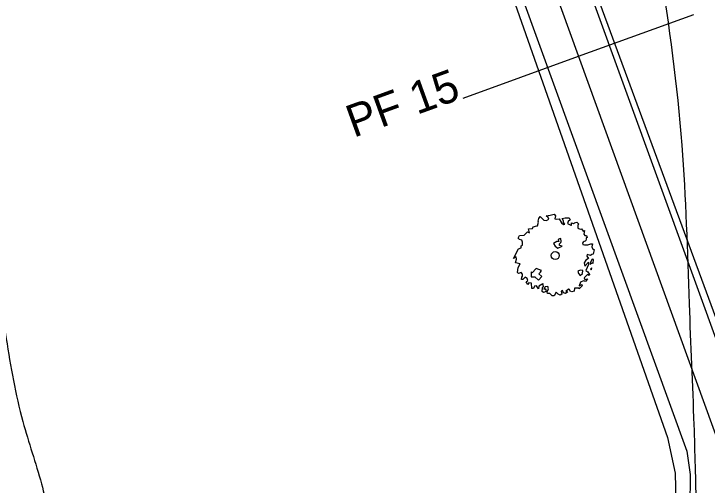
# Model space of a CAD drawing. Extents: x -475575 to -473225, y -1116053 to -1114104.
# Drawn here: x -474251.65 to -474209.3, y -1115030.45 to -1115001.67 of the extents above; entities that cross this region are included whole.
import ezdxf

# ---------------------------------------------------------------- set-up
doc = ezdxf.new("R2010")
doc.units = 0
for name, color, linetype in [('CESTN___P____KOP_N__VRH__Construction_', 7, 'Continuous'), ('IP', 7, 'Continuous'), ('POLYGONY_SITUACE_PF', 7, 'Continuous'), ('POLYGONY_SITUACE_PF_POPISY', 7, 'Continuous'), ('POLYGONY_SITUACE_PO', 7, 'Continuous'), ('Vrstevnice_vedlejsi', 7, 'Continuous')]:
    doc.layers.add(name, color=color, linetype=linetype)

msp = doc.modelspace()

# ---------------------------------------------------------------- linework, layer by layer
at = {"layer": 'CESTN___P____KOP_N__VRH__Construction_'}
for p, q in [((-474246.987, -1114927.857), (-474210.542, -1115028.369)), ((-474231.637, -1114958.457), (-474205.729, -1115029.905)), ((-474205.264, -1115029.737), (-474231.546, -1114958.425)), ((-474235.524, -1114959.867), (-474211.725, -1115027.539)), ((-474211.725, -1115027.539), (-474211.259, -1115029.711)), ((-474210.542, -1115028.369), (-474210.339, -1115029.807)), ((-474211.259, -1115029.711), (-474211.209, -1115031.692))]:
    msp.add_line(p, q, dxfattribs=at)
msp.add_lwpolyline([(-474210.339, -1115029.807), (-474210.35, -1115031.791), (-474211.002, -1115034.077), (-474212.269, -1115036.076), (-474213.446, -1115037.508), (-474215.891, -1115039.468), (-474220.325, -1115041.214)], dxfattribs=at)
at = {"layer": 'IP'}
for points in [[(-474216.608, -1115017.857), (-474216.722, -1115018.006), (-474216.851, -1115017.972), (-474217.027, -1115018.063), (-474217.123, -1115018.272), (-474216.952, -1115018.206), (-474216.928, -1115018.284), (-474217.121, -1115018.463), (-474217.11, -1115018.428), (-474217.406, -1115018.415), (-474217.426, -1115018.596), (-474217.556, -1115018.636), (-474217.674, -1115018.613), (-474217.698, -1115018.509), (-474217.769, -1115018.479), (-474217.922, -1115018.631), (-474217.798, -1115018.652), (-474217.94, -1115018.745), (-474218.075, -1115018.708), (-474218.125, -1115018.555), (-474218.219, -1115018.602), (-474218.177, -1115018.795), (-474218.27, -1115018.849), (-474218.407, -1115018.791), (-474218.52, -1115018.673), (-474218.649, -1115018.886), (-474218.771, -1115018.882), (-474218.9, -1115018.739), (-474219.055, -1115018.754), (-474219.079, -1115018.646), (-474218.988, -1115018.455), (-474219.036, -1115018.311), (-474219.195, -1115018.336), (-474219.28, -1115018.472), (-474219.196, -1115018.461), (-474219.158, -1115018.529), (-474219.14, -1115018.619), (-474219.293, -1115018.691), (-474219.382, -1115018.626), (-474219.352, -1115018.401), (-474219.301, -1115018.324), (-474219.328, -1115018.132), (-474219.336, -1115018.152), (-474219.585, -1115018.293), (-474219.606, -1115018.456), (-474219.729, -1115018.268), (-474219.85, -1115018.306), (-474219.906, -1115018.439), (-474220.004, -1115018.436), (-474220.02, -1115018.11), (-474220.18, -1115018.103), (-474220.257, -1115018.194), (-474220.351, -1115018.031), (-474220.25, -1115017.962), (-474220.282, -1115017.825), (-474220.405, -1115017.744), (-474220.553, -1115017.886), (-474220.64, -1115017.888), (-474220.62, -1115017.753), (-474220.574, -1115017.682), (-474220.579, -1115017.561), (-474220.662, -1115017.454), (-474220.821, -1115017.531), (-474220.882, -1115017.465), (-474220.849, -1115017.155), (-474220.727, -1115016.926), (-474220.997, -1115016.867), (-474220.942, -1115016.658), (-474220.959, -1115016.512), (-474221.127, -1115016.605), (-474220.828, -1115016.028), (-474220.666, -1115015.959), (-474220.66, -1115015.829), (-474220.585, -1115015.802), (-474220.581, -1115015.621), (-474220.608, -1115015.484), (-474220.765, -1115015.455), (-474220.835, -1115015.368), (-474220.755, -1115015.212), (-474220.471, -1115015.18), (-474220.269, -1115014.972), (-474220.157, -1115015.032), (-474220.202, -1115014.788), (-474219.957, -1115014.771), (-474219.93, -1115014.683), (-474219.706, -1115014.62), (-474219.653, -1115014.62), (-474219.59, -1115014.389), (-474219.628, -1115014.323), (-474219.57, -1115014.165), (-474219.489, -1115014.039), (-474219.279, -1115014.275), (-474219.113, -1115014.281), (-474218.97, -1115014.213), (-474219.005, -1115014.104), (-474219.132, -1115013.998), (-474218.894, -1115013.967), (-474218.647, -1115013.907), (-474218.56, -1115014.004), (-474218.601, -1115014.193), (-474218.477, -1115014.212), (-474218.327, -1115014.18), (-474218.193, -1115014.438), (-474218.079, -1115014.536), (-474217.985, -1115014.518), (-474218.062, -1115014.42), (-474218.062, -1115014.306), (-474218.146, -1115014.171), (-474217.972, -1115014.117), (-474217.719, -1115014.132), (-474217.671, -1115014.252), (-474217.791, -1115014.355), (-474217.831, -1115014.464), (-474217.621, -1115014.566), (-474217.585, -1115014.576), (-474217.583, -1115014.421), (-474217.465, -1115014.48), (-474217.392, -1115014.435), (-474217.262, -1115014.392), (-474217.159, -1115014.482), (-474217.204, -1115014.585), (-474217.187, -1115014.764), (-474217.048, -1115014.808), (-474216.962, -1115014.79), (-474216.874, -1115014.948), (-474216.781, -1115014.908), (-474216.824, -1115015.113), (-474216.772, -1115015.204), (-474216.668, -1115015.199), (-474216.623, -1115015.334), (-474216.693, -1115015.348), (-474216.686, -1115015.43), (-474216.713, -1115015.518), (-474216.751, -1115015.552), (-474216.817, -1115015.567), (-474216.877, -1115015.609), (-474216.919, -1115015.663), (-474216.895, -1115015.747), (-474216.795, -1115015.783), (-474216.575, -1115015.784), (-474216.405, -1115015.71), (-474216.3, -1115015.719), (-474216.331, -1115015.901), (-474216.286, -1115016.031), (-474216.208, -1115016.062), (-474216.269, -1115016.335), (-474216.337, -1115016.357), (-474216.432, -1115016.419), (-474216.63, -1115016.364), (-474216.638, -1115016.463), (-474216.55, -1115016.618), (-474216.708, -1115016.716), (-474216.818, -1115016.882), (-474216.775, -1115017.084), (-474216.552, -1115016.83), (-474216.54, -1115016.965), (-474216.717, -1115017.343), (-474216.582, -1115017.425), (-474216.482, -1115017.593), (-474216.502, -1115017.639), (-474216.606, -1115017.59), (-474216.81, -1115017.799), (-474216.766, -1115017.894)], [(-474218.337, -1115015.565), (-474218.48, -1115015.565), (-474218.681, -1115015.694), (-474218.585, -1115015.846), (-474218.41, -1115015.973), (-474218.15, -1115015.851), (-474218.326, -1115015.82), (-474218.308, -1115015.718), (-474218.238, -1115015.622), (-474218.208, -1115015.58), (-474218.23, -1115015.392), (-474218.324, -1115015.404), (-474218.4, -1115015.454), (-474218.37, -1115015.527)], [(-474216.317, -1115016.659), (-474216.429, -1115016.836), (-474216.444, -1115016.951), (-474216.29, -1115016.877), (-474216.266, -1115016.909), (-474216.231, -1115016.662)], [(-474219.421, -1115017.334), (-474219.749, -1115017.22), (-474219.99, -1115017.481), (-474220.043, -1115017.431), (-474220.05, -1115017.721), (-474219.83, -1115017.727), (-474219.608, -1115017.935), (-474219.399, -1115017.714), (-474219.569, -1115017.554), (-474219.471, -1115017.451)], [(-474216.897, -1115017.341), (-474217.053, -1115017.314), (-474217.204, -1115017.391), (-474217.152, -1115017.53), (-474217.048, -1115017.639), (-474216.911, -1115017.526)], [(-474216.35, -1115017.184), (-474216.429, -1115017.26), (-474216.391, -1115017.308), (-474216.357, -1115017.284)]]:
    msp.add_lwpolyline(points, close=True, dxfattribs=at)
msp.add_circle((-474218.577, -1115016.428), 0.247, dxfattribs=at)
at = {"layer": 'POLYGONY_SITUACE_PF'}
msp.add_lwpolyline([(-474224.205, -1115006.821), (-474217.154, -1115004.264), (-474210.104, -1115001.707)], dxfattribs=at)
at = {"layer": 'POLYGONY_SITUACE_PO'}
msp.add_lwpolyline([(-474033.93, -1115484.017), (-474028.81, -1115469.55), (-474027.706, -1115465.586), (-474027.155, -1115461.509), (-474027.167, -1115457.394), (-474027.702, -1115449.947), (-474028.133, -1115446.706), (-474028.952, -1115443.542), (-474030.148, -1115440.499), (-474155.776, -1115170.193), (-474159.336, -1115162.232), (-474162.663, -1115154.172), (-474165.754, -1115146.018), (-474287.504, -1114810.25), (-474291.915, -1114795.876)], dxfattribs=at)
at = {"layer": 'Vrstevnice_vedlejsi'}
for points in [[(-474198.341, -1114669.49), (-474196.681, -1114672.256), (-474195.18, -1114674.653), (-474193.836, -1114676.681), (-474192.651, -1114678.341), (-474192.443, -1114683.526), (-474193.214, -1114692.237), (-474194.962, -1114704.473), (-474196.31, -1114712.997), (-474197.258, -1114717.807), (-474197.807, -1114718.903), (-474198.355, -1114720.033), (-474198.903, -1114721.196), (-474199.452, -1114722.393), (-474202.29, -1114724.764), (-474207.417, -1114728.309), (-474214.834, -1114733.029), (-474221.352, -1114738.648), (-474226.971, -1114745.166), (-474231.691, -1114752.583), (-474235.037, -1114757.727), (-474237.009, -1114760.598), (-474237.607, -1114761.196), (-474238.205, -1114762.022), (-474238.804, -1114763.076), (-474239.402, -1114764.358), (-474242.028, -1114769.031), (-474246.681, -1114777.093), (-474253.362, -1114788.547), (-474258.559, -1114799.152), (-474262.27, -1114808.908), (-474264.497, -1114817.816), (-474266.676, -1114825.23), (-474268.807, -1114831.15), (-474270.889, -1114835.575), (-474272.278, -1114842.188), (-474272.972, -1114850.991), (-474272.972, -1114861.981), (-474273.054, -1114870.089), (-474273.218, -1114875.314), (-474273.465, -1114877.657), (-474273.273, -1114882.608), (-474272.641, -1114890.167), (-474271.571, -1114900.334), (-474271.061, -1114908.167), (-474271.11, -1114913.667), (-474271.719, -1114916.834), (-474271.646, -1114922.058), (-474270.891, -1114929.339), (-474269.454, -1114938.678), (-474268.091, -1114946.236), (-474266.802, -1114952.012), (-474265.586, -1114956.006), (-474264.292, -1114960.893), (-474262.92, -1114966.673), (-474261.469, -1114973.346), (-474259.897, -1114980.014), (-474258.202, -1114986.679), (-474256.386, -1114993.34), (-474254.916, -1115000.31), (-474253.793, -1115007.591), (-474253.017, -1115015.182), (-474252.121, -1115021.507), (-474251.104, -1115026.568), (-474249.968, -1115030.364), (-474249.22, -1115033.873), (-474248.86, -1115037.095), (-474248.889, -1115040.031), (-474248.926, -1115042.279), (-474248.97, -1115043.838), (-474249.022, -1115044.709), (-474249.185, -1115045.346), (-474249.46, -1115045.75), (-474249.845, -1115045.92), (-474250.053, -1115046.628), (-474250.085, -1115047.873), (-474249.939, -1115049.656), (-474250.24, -1115054.341), (-474250.987, -1115061.928), (-474252.18, -1115072.418), (-474252.552, -1115080.569), (-474252.103, -1115086.383), (-474250.833, -1115089.859), (-474248.888, -1115093.001), (-474246.267, -1115095.808), (-474242.971, -1115098.281), (-474237.53, -1115101.018), (-474229.942, -1115104.018), (-474220.207, -1115107.282), (-474212.554, -1115110.016), (-474206.982, -1115112.221), (-474203.491, -1115113.895), (-474200.507, -1115114.848), (-474198.031, -1115115.078), (-474196.062, -1115114.586), (-474193.634, -1115114.914), (-474190.746, -1115116.062)], [(-474106.724, -1115139.906), (-474105.975, -1115134.747), (-474104.91, -1115130.242), (-474103.528, -1115126.392), (-474101.829, -1115123.196), (-474101.248, -1115119.409), (-474101.786, -1115115.032), (-474103.442, -1115110.065), (-474106.201, -1115105.465), (-474110.065, -1115101.234), (-474115.032, -1115097.37), (-474120.595, -1115093.294), (-474126.753, -1115089.004), (-474133.506, -1115084.502), (-474139.856, -1115081.154), (-474145.801, -1115078.961), (-474151.342, -1115077.922), (-474155.382, -1115077.318), (-474157.922, -1115077.148), (-474158.961, -1115077.413), (-474159.927, -1115077.355), (-474160.82, -1115076.975), (-474161.64, -1115076.273), (-474163.375, -1115076.297), (-474166.027, -1115077.047), (-474169.593, -1115078.523), (-474174.953, -1115080.253), (-474182.107, -1115082.237), (-474191.053, -1115084.473), (-474198.277, -1115085.36), (-474203.777, -1115084.898), (-474207.554, -1115083.087), (-474210.582, -1115078.783), (-474212.862, -1115071.987), (-474214.394, -1115062.7), (-474215.425, -1115054.98), (-474215.955, -1115048.829), (-474215.985, -1115044.245), (-474215.583, -1115041.048), (-474214.749, -1115039.236), (-474213.484, -1115038.81), (-474212.393, -1115038.422), (-474211.477, -1115038.073), (-474210.736, -1115037.762), (-474210.235, -1115036.623), (-474209.974, -1115034.657), (-474209.953, -1115031.862), (-474210.087, -1115026.769), (-474210.376, -1115019.378), (-474210.819, -1115009.689), (-474212.181, -1114998.785), (-474214.462, -1114986.667), (-474217.662, -1114973.333), (-474220.697, -1114961.225), (-474223.567, -1114950.342), (-474226.271, -1114940.683), (-474228.65, -1114933.019), (-474230.705, -1114927.35), (-474232.434, -1114923.675), (-474233.1, -1114917.916), (-474232.704, -1114910.072), (-474231.244, -1114900.144), (-474229.766, -1114892.391), (-474228.27, -1114886.811), (-474226.756, -1114883.405), (-474225.554, -1114878.524), (-474224.663, -1114872.166), (-474224.082, -1114864.332), (-474222.871, -1114857.276), (-474221.027, -1114850.999), (-474218.553, -1114845.499), (-474216.392, -1114840.557), (-474214.547, -1114836.172), (-474213.015, -1114832.344), (-474210.719, -1114828.319), (-474207.656, -1114824.099), (-474203.828, -1114819.682), (-474200.394, -1114815.041), (-474197.354, -1114810.176), (-474194.708, -1114805.088), (-474192.13, -1114800), (-474189.62, -1114794.912), (-474187.178, -1114789.824), (-474182.801, -1114780.435), (-474176.49, -1114766.746), (-474168.245, -1114748.757), (-474162.295, -1114736.021), (-474158.639, -1114728.54), (-474157.277, -1114726.312), (-474156.001, -1114724.373), (-474154.81, -1114722.723), (-474153.704, -1114721.361), (-474151.414, -1114718.384), (-474147.941, -1114713.791), (-474143.284, -1114707.582), (-474139.388, -1114701.068), (-474136.252, -1114694.249)], [(-474227.218, -1115164.851), (-474226.448, -1115162.426), (-474227.525, -1115159.571), (-474230.451, -1115156.287), (-474235.226, -1115152.573), (-474240.399, -1115148.881), (-474245.971, -1115145.211), (-474251.942, -1115141.562), (-474256.818, -1115137.139), (-474260.6, -1115131.942), (-474263.287, -1115125.971), (-474265.918, -1115121.36), (-474268.492, -1115118.11), (-474271.011, -1115116.221), (-474273.409, -1115112.993), (-474275.686, -1115108.429), (-474277.843, -1115102.526), (-474279.974, -1115096.744), (-474282.078, -1115091.082), (-474284.156, -1115085.541), (-474285.812, -1115080.883), (-474287.047, -1115077.109), (-474287.86, -1115074.218), (-474288.244, -1115068.81), (-474288.198, -1115060.885), (-474287.724, -1115050.442), (-474287.488, -1115042.595), (-474287.491, -1115037.342), (-474287.732, -1115034.684), (-474288.91, -1115029.354), (-474291.024, -1115021.351), (-474294.074, -1115010.675), (-474297.009, -1115000.754), (-474299.828, -1114991.588), (-474302.532, -1114983.176), (-474304.676, -1114975.928), (-474306.261, -1114969.843), (-474307.286, -1114964.921), (-474309.265, -1114957.199), (-474312.198, -1114946.677), (-474316.084, -1114933.354), (-474318.675, -1114924.468), (-474319.971, -1114920.02), (-474319.973, -1114920.01), (-474319.977, -1114919.992), (-474319.984, -1114919.965), (-474319.992, -1114919.931), (-474321.301, -1114916.779), (-474323.911, -1114910.509), (-474327.823, -1114901.121), (-474333.571, -1114893.897), (-474341.156, -1114888.835), (-474350.578, -1114885.936), (-474361.246, -1114883.666), (-474373.16, -1114882.025), (-474386.32, -1114881.012), (-474395.152, -1114880.336), (-474399.654, -1114879.994), (-474399.827, -1114879.989), (-474403.877, -1114879.477), (-474411.805, -1114878.46), (-474423.609, -1114876.937), (-474431.988, -1114875.62), (-474436.942, -1114874.51), (-474438.471, -1114873.607), (-474443.932, -1114869.371), (-474453.324, -1114861.802), (-474466.647, -1114850.901), (-474475.533, -1114843.63), (-474479.981, -1114839.989), (-474479.99, -1114839.978), (-474480.008, -1114839.975), (-474480.035, -1114839.978), (-474480.069, -1114839.989), (-474480.092, -1114840.008), (-474480.104, -1114840.035), (-474480.104, -1114840.069), (-474483.152, -1114844.525), (-474489.247, -1114853.403), (-474498.39, -1114866.701), (-474505.505, -1114879.646), (-474510.592, -1114892.237), (-474513.651, -1114904.473), (-474515.798, -1114912.997), (-474517.033, -1114917.807), (-474517.355, -1114918.903), (-474517.71, -1114919.879), (-474518.097, -1114920.733), (-474518.517, -1114921.467), (-474518.841, -1114922.054), (-474519.069, -1114922.494), (-474519.202, -1114922.788), (-474519.513, -1114923.611), (-474520.002, -1114924.961), (-474520.669, -1114926.839), (-474521.912, -1114930.34), (-474523.73, -1114935.464)]]:
    msp.add_spline(points, degree=3, dxfattribs=at)

# ---------------------------------------------------------------- texts
at = {"layer": 'POLYGONY_SITUACE_PF_POPISY'}
msp.add_text('PF 15', height=1.9765, rotation=19.9307, dxfattribs=at).set_placement((-474230.894, -1115009.246))

doc.saveas('drawing.dxf')
